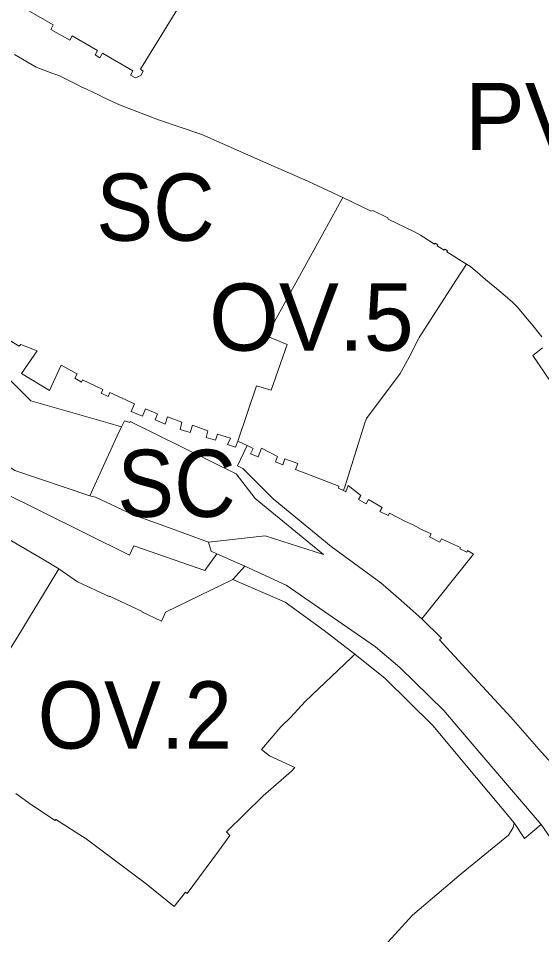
# Model space of a CAD drawing. Extents: x -650451 to -642268, y -1075216 to -1066610.
# Drawn here: x -647188.6 to -647095.1, y -1070735.3 to -1070571.6 of the extents above; entities that cross this region are included whole.
import ezdxf

# ---------------------------------------------------------------- set-up
doc = ezdxf.new("R2010")
doc.units = 0
doc.header["$LTSCALE"] = 4.8
for name, color, linetype, lineweight in [('11', 7, 'Continuous', 13), ('15', 7, 'Continuous', 13), ('17', 7, 'Continuous', 13), ('40', 7, 'Continuous', 13), ('45', 7, 'Continuous', 13)]:
    doc.layers.add(name, color=color, linetype=linetype, lineweight=lineweight)
doc.layers.add('62', color=7, linetype='Continuous')

msp = doc.modelspace()

# ---------------------------------------------------------------- linework, layer by layer
at = {"layer": '11'}
for points in [[(-647149.36, -1070647.12), (-647146.01, -1070637.28), (-647143.4, -1070638.03), (-647140.56, -1070629.88), (-647144, -1070628.42), (-647143.16, -1070626.45), (-647130.6, -1070603.65)], [(-647130.6, -1070603.65), (-647125.52, -1070606.06), (-647125.27, -1070605.94), (-647122.55, -1070607.27), (-647122.5, -1070607.52), (-647117.78, -1070609.73), (-647117.24, -1070610.04), (-647116.73, -1070610.37), (-647116.27, -1070610.65), (-647114.22, -1070611.94), (-647114.09, -1070611.78), (-647113.62, -1070612.07), (-647113.75, -1070612.23), (-647112.48, -1070613.02), (-647112.34, -1070612.85), (-647111.89, -1070613.14), (-647112.03, -1070613.3), (-647108.49, -1070615.51)], [(-647108.49, -1070615.51), (-647110.28, -1070618.29), (-647116.95, -1070628.64), (-647117.11, -1070628.88), (-647118.75, -1070632.14), (-647120.34, -1070635.07), (-647126.39, -1070643.09), (-647126.63, -1070643.69), (-647129.93, -1070654.36), (-647130.11, -1070654.96), (-647130.48, -1070655.97)], [(-647130.48, -1070655.97), (-647131.41, -1070655.51), (-647131.31, -1070655.15), (-647132.87, -1070654.56), (-647135.8, -1070653.46), (-647137.51, -1070652.81), (-647139.05, -1070652.22), (-647138.66, -1070651.14), (-647140.98, -1070650.29), (-647141.33, -1070651.36), (-647142.64, -1070650.83), (-647142.26, -1070649.85), (-647145.13, -1070648.4), (-647145.73, -1070649.93), (-647147.12, -1070649.39), (-647146.61, -1070648.47), (-647147.72, -1070647.92), (-647149.36, -1070647.12)], [(-647223.41, -1070703.66), (-647213.3, -1070701.31), (-647206.09, -1070695.93), (-647204.33, -1070697.84), (-647203.49, -1070697.13), (-647196.38, -1070691.15), (-647194.55, -1070689.63), (-647193.07, -1070688.41), (-647192.66, -1070688.03), (-647192.05, -1070687.52), (-647190.53, -1070685.01), (-647188.06, -1070680.95), (-647186.61, -1070678.56), (-647183.3, -1070673.12), (-647181.36, -1070669.94)], [(-647181.36, -1070669.94), (-647178.03, -1070672.27), (-647172.36, -1070674.9), (-647172.32, -1070674.81), (-647166.48, -1070677.54), (-647166.52, -1070677.63), (-647163.04, -1070679.27), (-647162.41, -1070677.95), (-647162.29, -1070677.69), (-647150.25, -1070671.84)], [(-647150.25, -1070671.84), (-647140.91, -1070675.91), (-647133.97, -1070680.96), (-647128.44, -1070685.21)], [(-647128.44, -1070685.21), (-647129.03, -1070685.79), (-647137.36, -1070693.65), (-647139.91, -1070696.44), (-647141.69, -1070698.18), (-647145.14, -1070702.18), (-647143.73, -1070703.33), (-647139.19, -1070705.45), (-647139.81, -1070706.05), (-647144.85, -1070710.47), (-647151.38, -1070716.93), (-647150.79, -1070717.57), (-647152.83, -1070720.39), (-647157.42, -1070726.56), (-647158.45, -1070727.92), (-647158.72, -1070727.7), (-647160.75, -1070730.22), (-647165.73, -1070726.2), (-647176.51, -1070718.19), (-647181.91, -1070714.71), (-647182.04, -1070714.9), (-647186.24, -1070712.1), (-647189.06, -1070710.05)]]:
    msp.add_lwpolyline(points, dxfattribs=at)
at = {"layer": '15'}
msp.add_line((-647149.36, -1070647.12), (-647147.72, -1070647.92), dxfattribs=at)
for points in [[(-647187.44, -1070569.87), (-647182.36, -1070572.78), (-647182.78, -1070573.6), (-647179.41, -1070575.5), (-647178.97, -1070574.74), (-647174.43, -1070577.38), (-647174.88, -1070578.16), (-647174.04, -1070578.65), (-647173.58, -1070577.87), (-647168.16, -1070581.01), (-647168.57, -1070581.76), (-647167.69, -1070582.24), (-647166.7, -1070581.81), (-647166.29, -1070581.03), (-647166.76, -1070580.72), (-647158.65, -1070567.47)], [(-647130.6, -1070603.65), (-647136.85, -1070600.72), (-647144.39, -1070597.43), (-647155.82, -1070592.35), (-647163.56, -1070589.75), (-647170.53, -1070587.07), (-647173.48, -1070585.68), (-647174.04, -1070585.41), (-647176.53, -1070584.24), (-647177.26, -1070583.9), (-647177.89, -1070583.58), (-647181.37, -1070581.86), (-647182.42, -1070581.46), (-647185.14, -1070580.45), (-647185.4, -1070580.35), (-647189.29, -1070578.11)], [(-647108.49, -1070615.51), (-647112.03, -1070613.3), (-647111.89, -1070613.14), (-647112.34, -1070612.85), (-647112.48, -1070613.02), (-647113.75, -1070612.23), (-647113.62, -1070612.07), (-647114.09, -1070611.78), (-647114.22, -1070611.94), (-647116.27, -1070610.65), (-647116.73, -1070610.37), (-647117.24, -1070610.04), (-647117.78, -1070609.73), (-647122.5, -1070607.52), (-647122.55, -1070607.27), (-647125.27, -1070605.94), (-647125.52, -1070606.06), (-647130.6, -1070603.65)], [(-647170.16, -1070644.59), (-647172.63, -1070643.88), (-647186.4, -1070639.91), (-647194.67, -1070631.67), (-647199.19, -1070627.76), (-647213.98, -1070616.48), (-647206.19, -1070630.4), (-647210.68, -1070637.17), (-647210.52, -1070637.52), (-647211.57, -1070637.9), (-647213.68, -1070641.13), (-647215.55, -1070640.03), (-647213.29, -1070636.7)], [(-647095.06, -1070628.49), (-647096.9, -1070626.19), (-647097.65, -1070625.28), (-647099.41, -1070623.22), (-647100.26, -1070622.32), (-647102.03, -1070620.82), (-647102.32, -1070620.58), (-647103.23, -1070619.8), (-647103.43, -1070619.64), (-647105.08, -1070618.24), (-647106.04, -1070617.42), (-647107.77, -1070615.96), (-647108.49, -1070615.51)], [(-647190.45, -1070628.98), (-647188.43, -1070630.2), (-647188.17, -1070629.87), (-647186.01, -1070630.72), (-647185.26, -1070631.02), (-647188.02, -1070635.07), (-647183.01, -1070638.11), (-647180.94, -1070633.55), (-647178.46, -1070634.93), (-647178.09, -1070635.13), (-647178.48, -1070635.89), (-647177.3, -1070636.6), (-647177.14, -1070636.2), (-647173.48, -1070637.92), (-647173.78, -1070638.59), (-647172.54, -1070639.19), (-647172.24, -1070638.43), (-647167.82, -1070640.48), (-647168.43, -1070641.82), (-647166.43, -1070642.7), (-647165.89, -1070641.39), (-647163.74, -1070642.25), (-647164.15, -1070643.35), (-647162.35, -1070644.09), (-647161.93, -1070642.77), (-647159.36, -1070643.72), (-647159.71, -1070645.08), (-647157.92, -1070645.58), (-647157.49, -1070644.28), (-647154.73, -1070645.32), (-647155.02, -1070646.46), (-647153.36, -1070646.97), (-647152.99, -1070645.86), (-647150.7, -1070646.6), (-647151.25, -1070647.76), (-647149.77, -1070648.22), (-647149.36, -1070647.12)], [(-647090.36, -1070641.15), (-647096.65, -1070631.82), (-647094.91, -1070630.5)], [(-647213.68, -1070641.13), (-647192.07, -1070655.98), (-647168.72, -1070667.48), (-647167.98, -1070665.84), (-647155.28, -1070670.24), (-647153.1, -1070667.29), (-647148.15, -1070669.49), (-647150.25, -1070671.84)], [(-647154.62, -1070665.19), (-647144.5, -1070664.05), (-647134.04, -1070667.4), (-647146.3, -1070657.36), (-647149.7, -1070652.96), (-647168.63, -1070643.63), (-647168.7, -1070643.78), (-647169.64, -1070643.53), (-647170.16, -1070644.59)], [(-647147.72, -1070647.92), (-647149.43, -1070651.57), (-647148.49, -1070652.05), (-647143.08, -1070657.43), (-647132.69, -1070665.98), (-647123.83, -1070672.44), (-647120.19, -1070675.58), (-647116.48, -1070678.87)], [(-647181.36, -1070669.94), (-647184.22, -1070668.24), (-647190.22, -1070664.68), (-647191.53, -1070663.9), (-647199.86, -1070658.73)], [(-647153.1, -1070667.29), (-647154.14, -1070666.77), (-647154.62, -1070665.19)], [(-647095.14, -1070715.62), (-647108.56, -1070699.95), (-647112.55, -1070695.23), (-647120.41, -1070687.57), (-647124.79, -1070683.89), (-647140.74, -1070672.88), (-647148.15, -1070669.49), (-647153.1, -1070667.29)], [(-647150.25, -1070671.84), (-647162.29, -1070677.69), (-647162.41, -1070677.95), (-647163.04, -1070679.27), (-647166.52, -1070677.63), (-647166.48, -1070677.54), (-647172.32, -1070674.81), (-647172.36, -1070674.9), (-647178.03, -1070672.27), (-647181.36, -1070669.94)], [(-647116.48, -1070678.87), (-647113, -1070682.34), (-647113.3, -1070682.6), (-647111.34, -1070684.76), (-647107.84, -1070688.58), (-647100.56, -1070696.42), (-647095.13, -1070702.61), (-647095.18, -1070702.65), (-647093.12, -1070704.85)], [(-647127.64, -1070742.17), (-647118.15, -1070731.8), (-647109.44, -1070724.44), (-647100.97, -1070717.49), (-647100.16, -1070716.12), (-647099.98, -1070715.28)], [(-647099.98, -1070715.28), (-647098.12, -1070718.12), (-647095.14, -1070715.62), (-647092.33, -1070719.64)], [(-647066.34, -1070738.73), (-647070.79, -1070736.62), (-647072.18, -1070736.18), (-647071.99, -1070735.71), (-647092.33, -1070719.64), (-647095.14, -1070715.62)]]:
    msp.add_lwpolyline(points, dxfattribs=at)
at = {"layer": '17'}
for points in [[(-647158.65, -1070567.47), (-647166.76, -1070580.72), (-647166.29, -1070581.03), (-647166.7, -1070581.81), (-647167.69, -1070582.24), (-647168.57, -1070581.76), (-647168.16, -1070581.01), (-647173.58, -1070577.87), (-647174.04, -1070578.65), (-647174.88, -1070578.16), (-647174.43, -1070577.38), (-647178.97, -1070574.74), (-647179.41, -1070575.5), (-647182.78, -1070573.6), (-647182.36, -1070572.78), (-647187.44, -1070569.87)], [(-647189.29, -1070578.11), (-647185.4, -1070580.35), (-647185.14, -1070580.45), (-647182.42, -1070581.46), (-647181.37, -1070581.86), (-647177.89, -1070583.58), (-647177.26, -1070583.9), (-647176.53, -1070584.24), (-647174.04, -1070585.41), (-647173.48, -1070585.68), (-647170.53, -1070587.07), (-647163.56, -1070589.75), (-647155.82, -1070592.35), (-647144.39, -1070597.43), (-647136.85, -1070600.72), (-647130.6, -1070603.65)], [(-647130.6, -1070603.65), (-647143.16, -1070626.45), (-647144, -1070628.42), (-647140.56, -1070629.88), (-647143.4, -1070638.03), (-647146.01, -1070637.28), (-647149.36, -1070647.12)], [(-647130.48, -1070655.97), (-647130.11, -1070654.96), (-647129.93, -1070654.36), (-647126.63, -1070643.69), (-647126.39, -1070643.09), (-647120.34, -1070635.07), (-647118.75, -1070632.14), (-647117.11, -1070628.88), (-647116.95, -1070628.64), (-647110.28, -1070618.29), (-647108.49, -1070615.51)], [(-647108.49, -1070615.51), (-647107.77, -1070615.96), (-647106.04, -1070617.42), (-647105.08, -1070618.24), (-647103.43, -1070619.64), (-647103.23, -1070619.8), (-647102.32, -1070620.58), (-647102.03, -1070620.82), (-647100.26, -1070622.32), (-647099.41, -1070623.22), (-647097.65, -1070625.28), (-647096.9, -1070626.19), (-647095.06, -1070628.49)], [(-647149.36, -1070647.12), (-647149.77, -1070648.22), (-647151.25, -1070647.76), (-647150.7, -1070646.6), (-647152.99, -1070645.86), (-647153.36, -1070646.97), (-647155.02, -1070646.46), (-647154.73, -1070645.32), (-647157.49, -1070644.28), (-647157.92, -1070645.58), (-647159.71, -1070645.08), (-647159.36, -1070643.72), (-647161.93, -1070642.77), (-647162.35, -1070644.09), (-647164.15, -1070643.35), (-647163.74, -1070642.25), (-647165.89, -1070641.39), (-647166.43, -1070642.7), (-647168.43, -1070641.82), (-647167.82, -1070640.48), (-647172.24, -1070638.43), (-647172.54, -1070639.19), (-647173.78, -1070638.59), (-647173.48, -1070637.92), (-647177.14, -1070636.2), (-647177.3, -1070636.6), (-647178.48, -1070635.89), (-647178.09, -1070635.13), (-647178.46, -1070634.93), (-647180.94, -1070633.55), (-647183.01, -1070638.11), (-647188.02, -1070635.07), (-647185.26, -1070631.02), (-647186.01, -1070630.72), (-647188.17, -1070629.87), (-647188.43, -1070630.2), (-647190.45, -1070628.98)], [(-647094.91, -1070630.5), (-647096.65, -1070631.82), (-647090.36, -1070641.15)], [(-647175.83, -1070656.89), (-647170.96, -1070646.21), (-647170.16, -1070644.59)], [(-647170.16, -1070644.59), (-647169.64, -1070643.53), (-647168.7, -1070643.78), (-647168.63, -1070643.63), (-647149.7, -1070652.96), (-647146.3, -1070657.36), (-647134.04, -1070667.4), (-647144.5, -1070664.05), (-647154.62, -1070665.19)], [(-647116.48, -1070678.87), (-647107.25, -1070667.35), (-647108.35, -1070666.67), (-647108.45, -1070666.94), (-647109.67, -1070666.38), (-647109.57, -1070666.11), (-647110.64, -1070665.68), (-647112.95, -1070664.59), (-647113.25, -1070665.15), (-647115.14, -1070664.23), (-647114.83, -1070663.71), (-647116.54, -1070662.9), (-647118.05, -1070662.07), (-647119.42, -1070661.46), (-647122.28, -1070659.99), (-647122.53, -1070660.43), (-647124.01, -1070659.68), (-647123.57, -1070659.01), (-647125.99, -1070657.57), (-647126.44, -1070658.31), (-647127.81, -1070657.58), (-647127.37, -1070656.83), (-647129.68, -1070655.05), (-647130.1, -1070656.16), (-647130.48, -1070655.97)], [(-647154.62, -1070665.19), (-647163.1, -1070662.08), (-647168.06, -1070660.27), (-647174.79, -1070657.16), (-647175.83, -1070656.89)], [(-647199.86, -1070658.73), (-647191.53, -1070663.9), (-647190.22, -1070664.68), (-647184.22, -1070668.24), (-647181.36, -1070669.94)], [(-647181.36, -1070669.94), (-647183.3, -1070673.12), (-647186.61, -1070678.56), (-647188.06, -1070680.95), (-647190.53, -1070685.01), (-647192.05, -1070687.52), (-647192.66, -1070688.03), (-647193.07, -1070688.41), (-647194.55, -1070689.63), (-647196.38, -1070691.15), (-647203.49, -1070697.13), (-647204.33, -1070697.84), (-647206.09, -1070695.93), (-647213.3, -1070701.31), (-647223.41, -1070703.66)], [(-647093.12, -1070704.85), (-647095.18, -1070702.65), (-647095.13, -1070702.61), (-647100.56, -1070696.42), (-647107.84, -1070688.58), (-647111.34, -1070684.76), (-647113.3, -1070682.6), (-647113, -1070682.34), (-647116.48, -1070678.87)], [(-647189.06, -1070710.05), (-647186.24, -1070712.1), (-647182.04, -1070714.9), (-647181.91, -1070714.71), (-647176.51, -1070718.19), (-647165.73, -1070726.2), (-647160.75, -1070730.22), (-647158.72, -1070727.7), (-647158.45, -1070727.92), (-647157.42, -1070726.56), (-647152.83, -1070720.39), (-647150.79, -1070717.57), (-647151.38, -1070716.93), (-647144.85, -1070710.47), (-647139.81, -1070706.05), (-647139.19, -1070705.45), (-647143.73, -1070703.33), (-647145.14, -1070702.18), (-647141.69, -1070698.18), (-647139.91, -1070696.44), (-647137.36, -1070693.65), (-647129.03, -1070685.79), (-647128.44, -1070685.21)], [(-647128.44, -1070685.21), (-647123.04, -1070689.52), (-647114.5, -1070697.91), (-647106.71, -1070707.26), (-647099.98, -1070715.28)], [(-647099.98, -1070715.28), (-647100.16, -1070716.12), (-647100.97, -1070717.49), (-647109.44, -1070724.44), (-647118.15, -1070731.8), (-647127.64, -1070742.17)]]:
    msp.add_lwpolyline(points, dxfattribs=at)
at = {"layer": '40'}
for points in [[(-647211.57, -1070637.9), (-647210.52, -1070637.52), (-647210.68, -1070637.17), (-647206.19, -1070630.4), (-647213.98, -1070616.48), (-647199.19, -1070627.76), (-647194.67, -1070631.67), (-647186.4, -1070639.91), (-647172.63, -1070643.88), (-647170.16, -1070644.59)], [(-647175.83, -1070656.89), (-647189.25, -1070652.4), (-647211.57, -1070637.9)], [(-647170.16, -1070644.59), (-647170.96, -1070646.21), (-647175.83, -1070656.89)], [(-647116.48, -1070678.87), (-647120.19, -1070675.58), (-647123.83, -1070672.44), (-647132.69, -1070665.98), (-647143.08, -1070657.43), (-647148.49, -1070652.05), (-647149.43, -1070651.57), (-647147.72, -1070647.92)], [(-647147.72, -1070647.92), (-647146.61, -1070648.47), (-647147.12, -1070649.39), (-647145.73, -1070649.93), (-647145.13, -1070648.4), (-647142.26, -1070649.85), (-647142.64, -1070650.83), (-647141.33, -1070651.36), (-647140.98, -1070650.29), (-647138.66, -1070651.14), (-647139.05, -1070652.22), (-647137.51, -1070652.81), (-647135.8, -1070653.46), (-647132.87, -1070654.56), (-647131.31, -1070655.15), (-647131.41, -1070655.51), (-647130.48, -1070655.97)], [(-647130.48, -1070655.97), (-647130.1, -1070656.16), (-647129.68, -1070655.05), (-647127.37, -1070656.83), (-647127.81, -1070657.58), (-647126.44, -1070658.31), (-647125.99, -1070657.57), (-647123.57, -1070659.01), (-647124.01, -1070659.68), (-647122.53, -1070660.43), (-647122.28, -1070659.99), (-647119.42, -1070661.46), (-647118.05, -1070662.07), (-647116.54, -1070662.9), (-647114.83, -1070663.71), (-647115.14, -1070664.23), (-647113.25, -1070665.15), (-647112.95, -1070664.59), (-647110.64, -1070665.68), (-647109.57, -1070666.11), (-647109.67, -1070666.38), (-647108.45, -1070666.94), (-647108.35, -1070666.67), (-647107.25, -1070667.35), (-647116.48, -1070678.87)]]:
    msp.add_lwpolyline(points, dxfattribs=at)
at = {"layer": '45'}
msp.add_line((-647150.25, -1070671.84), (-647148.15, -1070669.49), dxfattribs=at)
for points in [[(-647211.57, -1070637.9), (-647189.25, -1070652.4), (-647175.83, -1070656.89)], [(-647153.1, -1070667.29), (-647155.28, -1070670.24), (-647167.98, -1070665.84), (-647168.72, -1070667.48), (-647192.07, -1070655.98), (-647213.68, -1070641.13)], [(-647175.83, -1070656.89), (-647174.79, -1070657.16), (-647168.06, -1070660.27), (-647163.1, -1070662.08), (-647154.62, -1070665.19)], [(-647154.62, -1070665.19), (-647154.14, -1070666.77), (-647153.1, -1070667.29)], [(-647148.15, -1070669.49), (-647140.74, -1070672.88), (-647124.79, -1070683.89), (-647120.41, -1070687.57), (-647112.55, -1070695.23), (-647108.56, -1070699.95), (-647095.14, -1070715.62)], [(-647128.44, -1070685.21), (-647133.97, -1070680.96), (-647140.91, -1070675.91), (-647150.25, -1070671.84)], [(-647099.98, -1070715.28), (-647106.71, -1070707.26), (-647114.5, -1070697.91), (-647123.04, -1070689.52), (-647128.44, -1070685.21)], [(-647095.14, -1070715.62), (-647098.12, -1070718.12), (-647099.98, -1070715.28)]]:
    msp.add_lwpolyline(points, dxfattribs=at)

# ---------------------------------------------------------------- texts
at = {"layer": '62'}
for s, p in [('PV', (-647108.785, -1070595.151)), ('OV.5', (-647154.506, -1070630.972))]:
    msp.add_text(s, height=12, dxfattribs=at).set_placement(p)
at = {"layer": '62', "width": 0.95}
for s, p in [('SC', (-647174.683, -1070611.345)), ('SC', (-647170.932, -1070660.67)), ('OV.2', (-647185.149, -1070702.042))]:
    msp.add_text(s, height=12, dxfattribs=at).set_placement(p)

doc.saveas('drawing.dxf')
